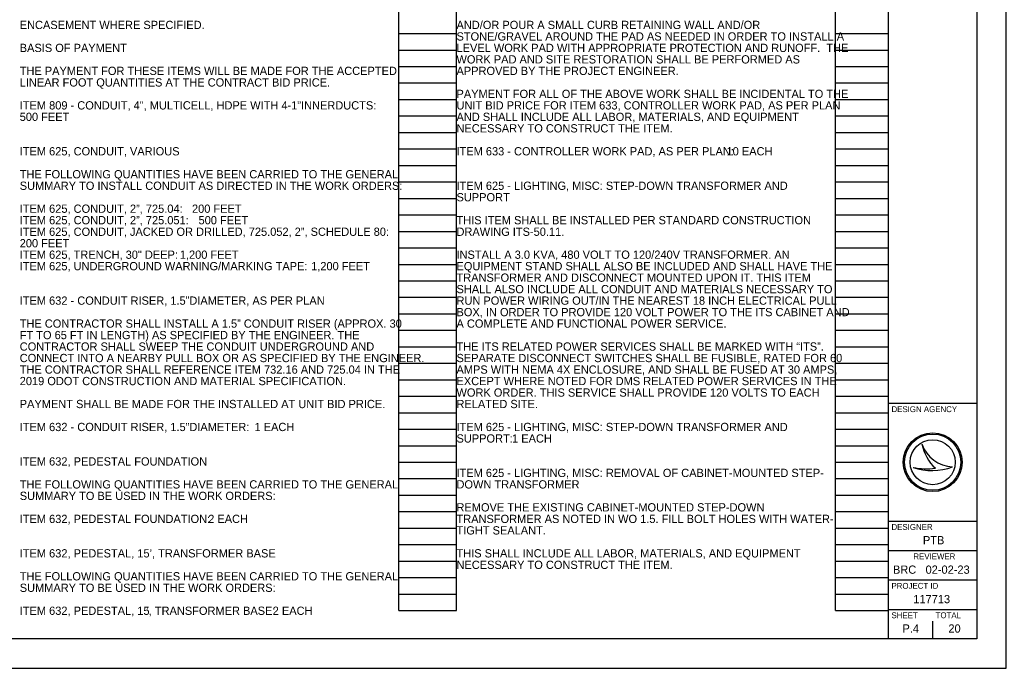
# Model space of a CAD drawing. Extents: x 0 to 34, y 0 to 22.
# Drawn here: x 17.24 to 34, y 0 to 11.01 of the extents above; entities that cross this region are included whole.
import ezdxf

# ---------------------------------------------------------------- set-up
doc = ezdxf.new("R2010")
doc.units = 0
for name, color, linetype in [('SH_Border', 7, 'Continuous'), ('SH_Cut_Line', 7, 'Continuous'), ('SH_Data', 7, 'Continuous'), ('SH_Text', 7, 'Continuous')]:
    doc.layers.add(name, color=color, linetype=linetype)

msp = doc.modelspace()

# ---------------------------------------------------------------- linework, layer by layer
at = {"layer": 'SH_Border'}
for p, q in [((32, 0.5), (32, 21.5)), ((32, 4.5), (33.5, 4.5)), ((32, 2.5), (33.5, 2.5)), ((32, 2), (33.5, 2)), ((32, 1.5), (33.5, 1.5)), ((32, 1), (33.5, 1))]:
    msp.add_line(p, q, dxfattribs=at)
msp.add_lwpolyline([(1.5, 21.5), (33.5, 21.5), (33.5, 0.5), (1.5, 0.5)], close=True, dxfattribs=at)
at = {"layer": 'SH_Cut_Line'}
msp.add_lwpolyline([(0, 0), (34, 0), (34, 22), (0, 22)], close=True, dxfattribs=at)
at = {"layer": 'SH_Data'}
for p, q in [((23.68, 0.98), (23.68, 21.14)), ((24.66, 0.98), (24.66, 21.14)), ((31.1, 0.98), (31.1, 21.14)), ((32, 0.98), (32, 21.14)), ((23.68, 10.78), (24.66, 10.78)), ((31.1, 10.78), (32, 10.78)), ((23.68, 10.5), (24.66, 10.5)), ((31.1, 10.5), (32, 10.5)), ((23.68, 10.22), (24.66, 10.22)), ((31.1, 10.22), (32, 10.22)), ((23.68, 9.94), (24.66, 9.94)), ((31.1, 9.94), (32, 9.94)), ((23.68, 9.66), (24.66, 9.66)), ((31.1, 9.66), (32, 9.66)), ((23.68, 9.38), (24.66, 9.38)), ((31.1, 9.38), (32, 9.38)), ((23.68, 9.1), (24.66, 9.1)), ((31.1, 9.1), (32, 9.1)), ((23.68, 8.82), (24.66, 8.82)), ((31.1, 8.82), (32, 8.82)), ((23.68, 8.54), (24.66, 8.54)), ((31.1, 8.54), (32, 8.54)), ((23.68, 8.26), (24.66, 8.26)), ((31.1, 8.26), (32, 8.26)), ((23.68, 7.98), (24.66, 7.98)), ((31.1, 7.98), (32, 7.98)), ((23.68, 7.7), (24.66, 7.7)), ((31.1, 7.7), (32, 7.7)), ((23.68, 7.42), (24.66, 7.42)), ((31.1, 7.42), (32, 7.42)), ((23.68, 7.14), (24.66, 7.14)), ((31.1, 7.14), (32, 7.14)), ((23.68, 6.86), (24.66, 6.86)), ((31.1, 6.86), (32, 6.86)), ((23.68, 6.58), (24.66, 6.58)), ((31.1, 6.58), (32, 6.58)), ((23.68, 6.3), (24.66, 6.3)), ((31.1, 6.3), (32, 6.3)), ((23.68, 6.02), (24.66, 6.02)), ((31.1, 6.02), (32, 6.02)), ((23.68, 5.74), (24.66, 5.74)), ((31.1, 5.74), (32, 5.74)), ((23.68, 5.46), (24.66, 5.46)), ((31.1, 5.46), (32, 5.46)), ((23.68, 5.18), (24.66, 5.18)), ((31.1, 5.18), (32, 5.18)), ((23.68, 4.9), (24.66, 4.9)), ((31.1, 4.9), (32, 4.9)), ((23.68, 4.62), (24.66, 4.62)), ((31.1, 4.62), (32, 4.62)), ((23.68, 4.34), (24.66, 4.34)), ((31.1, 4.34), (32, 4.34)), ((23.68, 4.06), (24.66, 4.06)), ((31.1, 4.06), (32, 4.06)), ((23.68, 3.78), (24.66, 3.78)), ((31.1, 3.78), (32, 3.78)), ((32.567, 3.81), (32.567, 3.81)), ((23.68, 3.5), (24.66, 3.5)), ((31.1, 3.5), (32, 3.5)), ((32.417, 3.41), (32.417, 3.41)), ((32.75, 3.5), (32.75, 3.5)), ((33.087, 3.419), (33.087, 3.419)), ((23.68, 3.22), (24.66, 3.22)), ((31.1, 3.22), (32, 3.22)), ((23.68, 2.94), (24.66, 2.94)), ((31.1, 2.94), (32, 2.94)), ((23.68, 2.66), (24.66, 2.66)), ((31.1, 2.66), (32, 2.66)), ((23.68, 2.38), (24.66, 2.38)), ((31.1, 2.38), (32, 2.38)), ((23.68, 2.1), (24.66, 2.1)), ((31.1, 2.1), (32, 2.1)), ((23.68, 1.82), (24.66, 1.82)), ((31.1, 1.82), (32, 1.82)), ((23.68, 1.54), (24.66, 1.54)), ((31.1, 1.54), (32, 1.54)), ((23.68, 1.26), (24.66, 1.26)), ((31.1, 1.26), (32, 1.26)), ((23.68, 0.98), (24.66, 0.98)), ((31.1, 0.98), (32, 0.98)), ((32.375, 0.675), (32.375, 0.675)), ((32.75, 0.5), (32.75, 0.8))]:
    msp.add_line(p, q, dxfattribs=at)
for radius in [0.5, 0.477, 0.477, 0.382]:
    msp.add_circle((32.75, 3.5), radius, dxfattribs=at)
for centre, radius, start, end in [((33.116, 3.998), 0.58, 198.9257, 198.9319), ((33.347, 3.97), 0.796, 191.6379, 191.6421), ((33.116, 3.998), 0.58, 198.9319, 267.1657), ((33.347, 3.97), 0.796, 191.6421, 226.0947), ((32.739, 4.37), 1.013, 251.4576, 290.0832), ((32.648, 4.654), 1.266, 259.4964, 259.4995), ((32.739, 4.37), 1.013, 251.4527, 251.4576), ((32.648, 4.654), 1.266, 259.4995, 276.6672)]:
    msp.add_arc(centre, radius, start, end, dxfattribs=at)

# ---------------------------------------------------------------- texts
for s, height, p in [('DESIGN AGENCY', 0.1, (32.05, 4.35)), ('DESIGNER', 0.1, (32.05, 2.35)), ('PTB', 0.14, (32.584, 2.105)), ('REVIEWER', 0.1, (32.422, 1.85)), ('BRC', 0.14, (32.075, 1.605)), ('02-02-23', 0.14, (32.629, 1.605)), ('PROJECT ID', 0.1, (32.05, 1.35)), ('117713', 0.14, (32.421, 1.105)), ('SHEET', 0.1, (32.05, 0.85)), ('TOTAL', 0.1, (32.8, 0.85)), ('P.4', 0.14, (32.237, 0.605)), ('20', 0.14, (33.017, 0.605))]:
    msp.add_text(s, height=height, dxfattribs=at).set_placement(p)
at = {"layer": 'SH_Text'}
for s, p in [('ENCASEMENT WHERE SPECIFIED.', (17.24, 10.856)), ('AND/OR POUR A SMALL CURB RETAINING WALL AND/OR ', (24.66, 10.856)), ('STONE/GRAVEL AROUND THE PAD AS NEEDED IN ORDER TO INSTALL A ', (24.66, 10.661)), ('BASIS OF PAYMENT', (17.24, 10.466)), ('LEVEL WORK PAD WITH APPROPRIATE PROTECTION AND RUNOFF.  THE ', (24.66, 10.466)), ('WORK PAD AND SITE RESTORATION SHALL BE PERFORMED AS ', (24.66, 10.271)), ('THE PAYMENT FOR THESE ITEMS WILL BE MADE FOR THE ACCEPTED ', (17.24, 10.076)), ('APPROVED BY THE PROJECT ENGINEER.', (24.66, 10.076)), ('LINEAR FOOT QUANTITIES AT THE CONTRACT BID PRICE.', (17.24, 9.88)), ('PAYMENT FOR ALL OF THE ABOVE WORK SHALL BE INCIDENTAL TO THE ', (24.66, 9.685)), ('ITEM 809 - CONDUIT, 4", MULTICELL, HDPE WITH 4-1”INNERDUCTS:', (17.24, 9.49)), ('UNIT BID PRICE FOR ITEM 633, CONTROLLER WORK PAD, AS PER PLAN ', (24.66, 9.49)), ('500 FEET', (17.24, 9.295)), ('AND SHALL INCLUDE ALL LABOR, MATERIALS, AND EQUIPMENT ', (24.66, 9.295)), ('NECESSARY TO CONSTRUCT THE ITEM.', (24.66, 9.1)), ('ITEM 625, CONDUIT, VARIOUS', (17.24, 8.71)), ('ITEM 633 - CONTROLLER WORK PAD, AS PER PLAN: ', (24.66, 8.71)), ('10 EACH', (29.248, 8.71)), ('THE FOLLOWING QUANTITIES HAVE BEEN CARRIED TO THE GENERAL ', (17.24, 8.32)), ('SUMMARY TO INSTALL CONDUIT AS DIRECTED IN THE WORK ORDERS:', (17.24, 8.125)), ('ITEM 625 - LIGHTING, MISC: STEP-DOWN TRANSFORMER AND ', (24.66, 8.125)), ('SUPPORT', (24.66, 7.93)), ('ITEM 625, CONDUIT, 2”, 725.04: ', (17.24, 7.735)), ('200 FEET', (20.167, 7.735)), ('ITEM 625, CONDUIT, 2”, 725.051: ', (17.24, 7.54)), ('500 FEET', (20.278, 7.54)), ('THIS ITEM SHALL BE INSTALLED PER STANDARD CONSTRUCTION ', (24.66, 7.54)), ('ITEM 625, CONDUIT, JACKED OR DRILLED, 725.052, 2”, SCHEDULE 80: ', (17.24, 7.344)), ('DRAWING ITS-50.11.', (24.66, 7.344)), ('200 FEET', (17.24, 7.149)), ('ITEM 625, TRENCH, 30" DEEP: ', (17.24, 6.954)), ('1,200 FEET', (19.96, 6.954)), ('INSTALL A 3.0 KVA, 480 VOLT TO 120/240V TRANSFORMER. AN ', (24.66, 6.954)), ('ITEM 625, UNDERGROUND WARNING/MARKING TAPE: ', (17.24, 6.759)), ('1,200 FEET', (22.191, 6.759)), ('EQUIPMENT STAND SHALL ALSO BE INCLUDED AND SHALL HAVE THE ', (24.66, 6.759)), ('TRANSFORMER AND DISCONNECT MOUNTED UPON IT. THIS ITEM ', (24.66, 6.564)), ('SHALL ALSO INCLUDE ALL CONDUIT AND MATERIALS NECESSARY TO ', (24.66, 6.369)), ('ITEM 632 - CONDUIT RISER, 1.5”DIAMETER, AS PER PLAN', (17.24, 6.174)), ('RUN POWER WIRING OUT/IN THE NEAREST 18 INCH ELECTRICAL PULL ', (24.66, 6.174)), ('BOX, IN ORDER TO PROVIDE 120 VOLT POWER TO THE ITS CABINET AND ', (24.66, 5.979)), ('THE CONTRACTOR SHALL INSTALL A 1.5” CONDUIT RISER (APPROX. 30 ', (17.24, 5.784)), ('A COMPLETE AND FUNCTIONAL POWER SERVICE.', (24.66, 5.784)), ('FT TO 65 FT IN LENGTH) AS SPECIFIED BY THE ENGINEER. THE ', (17.24, 5.589)), ('CONTRACTOR SHALL SWEEP THE CONDUIT UNDERGROUND AND ', (17.24, 5.394)), ('THE ITS RELATED POWER SERVICES SHALL BE MARKED WITH “ITS”. ', (24.66, 5.394)), ('CONNECT INTO A NEARBY PULL BOX OR AS SPECIFIED BY THE ENGINEER. ', (17.24, 5.199)), ('SEPARATE DISCONNECT SWITCHES SHALL BE FUSIBLE, RATED FOR 60 ', (24.66, 5.199)), ('THE CONTRACTOR SHALL REFERENCE ITEM 732.16 AND 725.04 IN THE ', (17.24, 5.003)), ('AMPS WITH NEMA 4X ENCLOSURE, AND SHALL BE FUSED AT 30 AMPS, ', (24.66, 5.003)), ('2019 ODOT CONSTRUCTION AND MATERIAL SPECIFICATION.', (17.24, 4.808)), ('EXCEPT WHERE NOTED FOR DMS RELATED POWER SERVICES IN THE ', (24.66, 4.808)), ('WORK ORDER. THIS SERVICE SHALL PROVIDE 120 VOLTS TO EACH ', (24.66, 4.613)), ('PAYMENT SHALL BE MADE FOR THE INSTALLED AT UNIT BID PRICE.', (17.24, 4.418)), ('RELATED SITE.', (24.66, 4.418)), ('ITEM 632 - CONDUIT RISER, 1.5”DIAMETER:  ', (17.24, 4.028)), ('1 EACH', (21.229, 4.028)), ('ITEM 625 - LIGHTING, MISC: STEP-DOWN TRANSFORMER AND ', (24.66, 4.028)), ('SUPPORT: ', (24.66, 3.833)), ('1 EACH', (25.604, 3.833)), ('ITEM 632, PEDESTAL FOUNDATION', (17.24, 3.443)), ('ITEM 625 - LIGHTING, MISC: REMOVAL OF CABINET-MOUNTED STEP-', (24.66, 3.248)), ('THE FOLLOWING QUANTITIES HAVE BEEN CARRIED TO THE GENERAL ', (17.24, 3.053)), ('DOWN TRANSFORMER', (24.66, 3.053)), ('SUMMARY TO BE USED IN THE WORK ORDERS:', (17.24, 2.858)), ('REMOVE THE EXISTING CABINET-MOUNTED STEP-DOWN ', (24.66, 2.663)), ('ITEM 632, PEDESTAL FOUNDATION:', (17.24, 2.467)), (' 2 EACH', (20.39, 2.467)), ('TRANSFORMER AS NOTED IN WO 1.5. FILL BOLT HOLES WITH WATER-', (24.66, 2.467)), ('TIGHT SEALANT.', (24.66, 2.272)), ('ITEM 632, PEDESTAL, 15’, TRANSFORMER BASE', (17.24, 1.882)), ('THIS SHALL INCLUDE ALL LABOR, MATERIALS, AND EQUIPMENT ', (24.66, 1.882)), ('NECESSARY TO CONSTRUCT THE ITEM.', (24.66, 1.687)), ('THE FOLLOWING QUANTITIES HAVE BEEN CARRIED TO THE GENERAL ', (17.24, 1.492)), ('SUMMARY TO BE USED IN THE WORK ORDERS:', (17.24, 1.297)), ('ITEM 632, PEDESTAL, 15', (17.24, 0.907)), ('’, TRANSFORMER BASE: ', (19.39, 0.907)), ('2 EACH', (21.538, 0.907))]:
    msp.add_text(s, height=0.14, dxfattribs=at).set_placement(p)

doc.saveas('drawing.dxf')
